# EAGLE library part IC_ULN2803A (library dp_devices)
DRIVER ARRAY
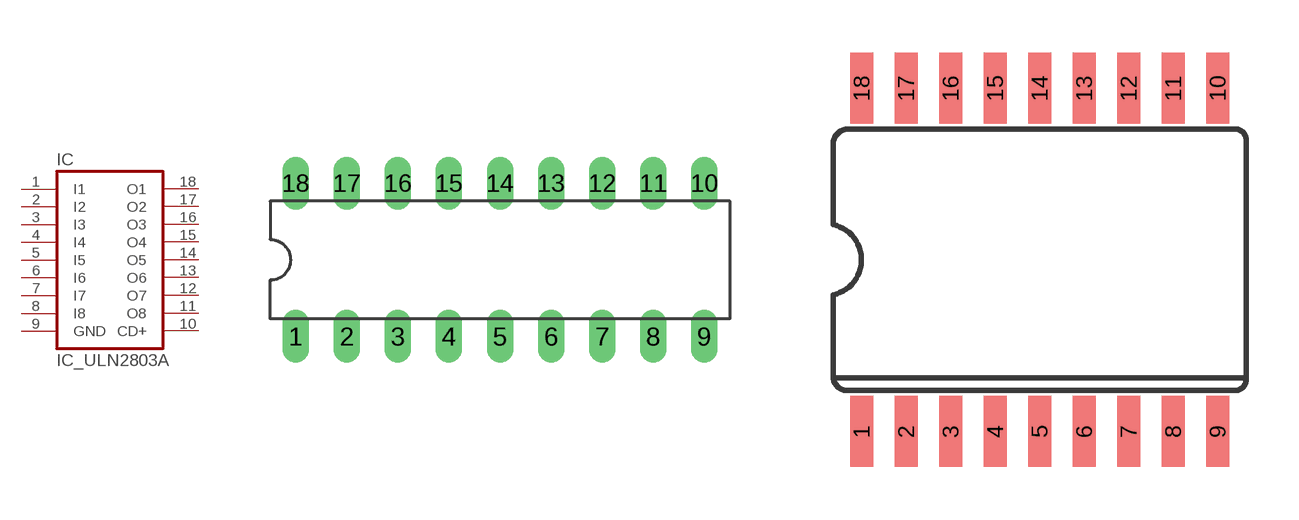
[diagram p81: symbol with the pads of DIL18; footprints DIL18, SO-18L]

Designator prefix IC

## IC_ULN2803AN  [DIL18]
1  I1  in
2  I2  in
3  I3  in
4  I4  in
5  I5  in
6  I6  in
7  I7  in
8  I8  in
9  GND  pwr
10  CD+  pas
11  O8  oc
12  O7  oc
13  O6  oc
14  O5  oc
15  O4  oc
16  O3  oc
17  O2  oc
18  O1  oc

## IC_ULN2803ADW  [SO-18L]
Pads as for DIL18

## IC_ULN2803A-SO-18  [SO-18]
Pads as for DIL18

## Footprint DIL18 (pad centres in mm)
Dual In Line Package
drill 0.813 long: 1 -10.16,-3.81; 2 -7.62,-3.81; 3 -5.08,-3.81; 4 -2.54,-3.81; 5 0,-3.81; 6 2.54,-3.81; 7 5.08,-3.81; 8 7.62,-3.81; 9 10.16,-3.81; 10 10.16,3.81; 11 7.62,3.81; 12 5.08,3.81; 13 2.54,3.81; 14 0,3.81; 15 -2.54,3.81; 16 -5.08,3.81; 17 -7.62,3.81; 18 -10.16,3.81

## Footprint SO-18L (pad centres in mm)
smd 0.66 x 2.032: 1 -4.445,-4.902; 2 -3.175,-4.902; 3 -1.905,-4.902; 4 -0.635,-4.902; 5 0.635,-4.902; 6 1.905,-4.902; 7 3.175,-4.902; 8 4.445,-4.902; 9 5.715,-4.902; 10 5.715,4.902; 11 4.445,4.902; 12 3.175,4.902; 13 1.905,4.902; 14 0.635,4.902; 15 -0.635,4.902; 16 -1.905,4.902; 17 -3.175,4.902; 18 -4.445,4.902

## Footprint SO-18 (pad centres in mm)
smd 0.66 x 2.032: 1 -5.08,-3.315; 2 -3.81,-3.315; 3 -2.54,-3.315; 4 -1.27,-3.315; 5 0,-3.315; 6 1.27,-3.315; 7 2.54,-3.315; 8 3.81,-3.315; 9 5.08,-3.353; 10 5.08,3.315; 11 3.81,3.315; 12 2.54,3.315; 13 1.27,3.315; 14 0,3.315; 15 -1.27,3.315; 16 -2.54,3.315; 17 -3.81,3.315; 18 -5.08,3.315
